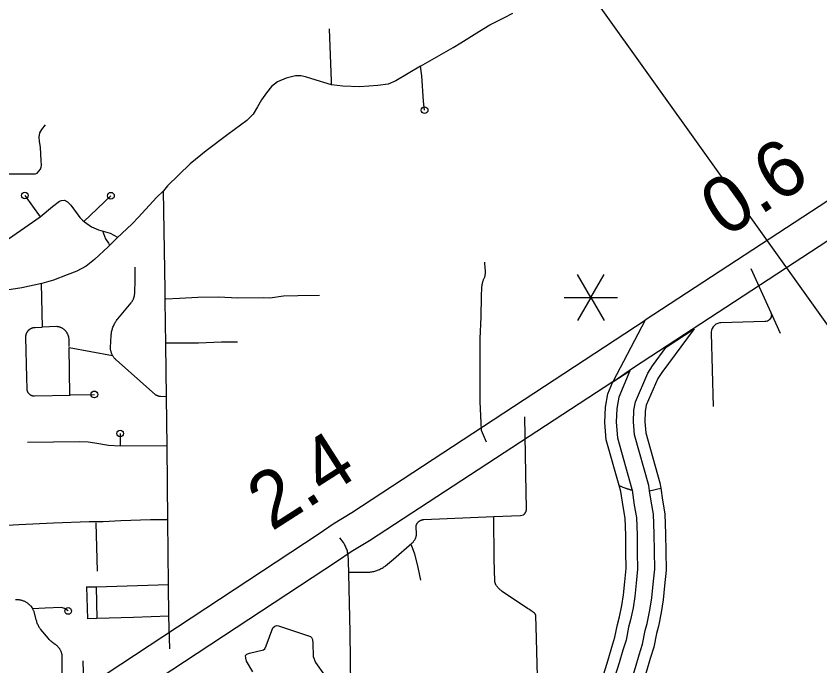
# Model space of a CAD drawing. Extents: x 309348 to 309445, y 336383 to 336484.
# Drawn here: x 309359.624 to 309362.374, y 336391.134 to 336393.355 of the extents above; entities that cross this region are included whole.
import ezdxf

# ---------------------------------------------------------------- set-up
doc = ezdxf.new("R2010")
doc.units = 0
doc.layers.add('R_Annotation', color=7, linetype='Continuous')

msp = doc.modelspace()

# ---------------------------------------------------------------- linework, layer by layer
at = {"layer": 'R_Annotation'}
for p, q in [((309361.5903, 336392.3927), (309361.5448, 336392.4715)), ((309361.5903, 336392.3927), (309361.6357, 336392.4715)), ((309361.4993, 336392.3927), (309361.5903, 336392.3927)), ((309361.5903, 336392.3927), (309361.5448, 336392.314)), ((309361.5903, 336392.3927), (309361.6812, 336392.3927)), ((309361.5903, 336392.3927), (309361.6357, 336392.314)), ((309361.8485, 336392.2227), (309361.9438, 336392.2861)), ((309361.666, 336392.1041), (309361.7243, 336392.1417))]:
    msp.add_line(p, q, dxfattribs=at)
for points in [[(309357.367, 336395.4603), (309360.1377, 336395.4603), (309363.8212, 336390.3132)], [(309367.0035, 336394.3488), (309366.123, 336394.2935), (309364.9553, 336394.2289), (309364.883, 336394.2195), (309364.8281, 336394.2076), (309364.6962, 336394.1686), (309364.597, 336394.1336), (309364.4828, 336394.0765), (309364.3887, 336394.0246), (309364.2, 336393.9054), (309364.1306, 336393.8579), (309362.6846, 336392.9078), (309361.7768, 336392.3157)], [(309361.7768, 336392.3157), (309361.666, 336392.1041), (309361.7366, 336392.1538), (309362.7468, 336392.8127), (309364.194, 336393.7635), (309364.2625, 336393.8105), (309364.4466, 336393.9267), (309364.5357, 336393.9759), (309364.6415, 336394.0288), (309364.7313, 336394.0604), (309364.8563, 336394.0974), (309364.9024, 336394.1074), (309364.9658, 336394.1157), (309366.1297, 336394.18), (309367.0106, 336394.2353)], [(309361.008, 336393.1834), (309361.1195, 336393.2475), (309361.1462, 336393.2636), (309361.2095, 336393.3036), (309361.2455, 336393.3243), (309361.2923, 336393.3491), (309361.324, 336393.3644)], [(309360.703, 336393.1196), (309360.7036, 336393.1323), (309360.6962, 336393.3114)], [(309361.008, 336393.1834), (309360.9229, 336393.133), (309360.8973, 336393.1223), (309360.8617, 336393.1174), (309360.7998, 336393.1131), (309360.7422, 336393.1152), (309360.703, 336393.1196), (309360.6356, 336393.1401), (309360.6142, 336393.1472), (309360.5979, 336393.1508), (309360.5801, 336393.1501), (309360.5481, 336393.143), (309360.5182, 336393.1295), (309360.4976, 336393.1145), (309360.4812, 336393.0925), (309360.4634, 336393.0683), (309360.4499, 336393.0441), (309360.435, 336393.0192), (309360.4137, 336392.9979), (309360.349, 336392.9502), (309360.275, 336392.8947), (309360.2195, 336392.8499), (309360.142, 336392.7745), (309360.1288, 336392.758)], [(309361.0218, 336393.0331), (309361.0181, 336393.0644), (309361.0118, 336393.1508), (309361.008, 336393.1834)], [(309359.5701, 336392.8087), (309359.5751, 336392.8137), (309359.5815, 336392.8153), (309359.6001, 336392.815), (309359.6739, 336392.8153), (309359.6902, 336392.816), (309359.6959, 336392.818), (309359.7019, 336392.8243), (309359.7075, 336392.8316), (309359.7099, 336392.8386), (309359.7109, 336392.8449), (309359.7105, 336392.8609), (309359.7082, 336392.9055), (309359.7042, 336392.9275), (309359.7029, 336392.9414), (309359.7052, 336392.9558), (309359.7122, 336392.9667), (309359.7245, 336392.983)], [(309359.6543, 336392.7415), (309359.7063, 336392.6687)], [(309359.8564, 336392.6528), (309359.9488, 336392.7408)], [(309359.9694, 336392.5958), (309360.0215, 336392.6449), (309360.0434, 336392.6674), (309360.1052, 336392.7341), (309360.1288, 336392.758)], [(309360.1348, 336392.3829), (309360.1344, 336392.4187), (309360.1288, 336392.758)], [(309359.7063, 336392.6687), (309359.7494, 336392.7041), (309359.7733, 336392.7217), (309359.7792, 336392.7246), (309359.7899, 336392.7256), (309359.8002, 336392.7197), (309359.8119, 336392.709), (309359.8427, 336392.666), (309359.851, 336392.6567), (309359.8578, 336392.6518), (309359.8818, 336392.6347), (309359.9062, 336392.6245), (309359.9467, 336392.6122), (309359.9716, 336392.5995)], [(309359.572, 336392.5752), (309359.7063, 336392.6687)], [(309359.9198, 336392.6204), (309359.9301, 336392.5937), (309359.9399, 336392.5781), (309359.9438, 336392.5722)], [(309359.939, 336392.5665), (309359.9694, 336392.5958)], [(309359.939, 336392.5665), (309359.893, 336392.5233), (309359.8637, 336392.5004), (309359.8319, 336392.4833), (309359.7992, 336392.4701), (309359.7523, 336392.452), (309359.7128, 336392.4408), (309359.6439, 336392.4261), (309359.6072, 336392.4203), (309359.5762, 336392.416)], [(309361.2271, 336392.514), (309361.2284, 336392.4911), (309361.2287, 336392.4888), (309361.229, 336392.4866), (309361.2291, 336392.4843), (309361.2292, 336392.4819), (309361.2292, 336392.4796), (309361.2291, 336392.4773), (309361.2289, 336392.475), (309361.2286, 336392.4728), (309361.2283, 336392.4705), (309361.2279, 336392.4682), (309361.2274, 336392.466), (309361.2269, 336392.4637), (309361.2263, 336392.4615), (309361.2256, 336392.4593), (309361.2248, 336392.4571), (309361.2237, 336392.455), (309361.2227, 336392.4528), (309361.2218, 336392.4506), (309361.221, 336392.4483), (309361.2202, 336392.446), (309361.2195, 336392.4437), (309361.2189, 336392.4414), (309361.2184, 336392.4391), (309361.2179, 336392.4367), (309361.2175, 336392.4343), (309361.2172, 336392.4319), (309361.217, 336392.4296), (309361.2168, 336392.4272), (309361.2154, 336392.397), (309361.2137, 336392.3254), (309361.2113, 336392.2526), (309361.2104, 336392.2222), (309361.2105, 336392.1803), (309361.2108, 336392.1076), (309361.2112, 336392.0362), (309361.2138, 336391.9643), (309361.2152, 336391.9392), (309361.2326, 336391.8992)], [(309360.0201, 336392.378), (309360.0211, 336392.3795), (309360.0221, 336392.3811), (309360.023, 336392.3826), (309360.0239, 336392.3842), (309360.0247, 336392.3859), (309360.0255, 336392.3875), (309360.0262, 336392.3892), (309360.0269, 336392.3909), (309360.0275, 336392.3926), (309360.0281, 336392.3944), (309360.0285, 336392.3961), (309360.029, 336392.3979), (309360.0293, 336392.3997), (309360.0296, 336392.4015), (309360.0299, 336392.4033), (309360.0301, 336392.4051), (309360.0302, 336392.407), (309360.0303, 336392.4088), (309360.032, 336392.4523), (309360.0312, 336392.4962)], [(309362.1381, 336392.4923), (309362.2063, 336392.3413), (309362.2067, 336392.3402), (309362.2078, 336392.3366), (309362.2082, 336392.3329), (309362.2079, 336392.3292), (309362.207, 336392.3255), (309362.2055, 336392.3221), (309362.2034, 336392.319), (309362.2008, 336392.3163), (309362.1978, 336392.314), (309362.1944, 336392.3124), (309362.1908, 336392.3113), (309362.1871, 336392.3109), (309362.1859, 336392.311), (309362.0351, 336392.3063), (309362.0306, 336392.3059), (309362.0244, 336392.3042), (309362.0186, 336392.3014), (309362.0134, 336392.2976), (309362.0091, 336392.2928), (309362.0057, 336392.2873), (309362.0034, 336392.2813), (309362.0023, 336392.2749), (309362.0023, 336392.2715), (309362.0089, 336392.0198)], [(309359.7101, 336392.4402), (309359.7133, 336392.2917)], [(309359.9544, 336392.1949), (309359.9535, 336392.1967), (309359.9526, 336392.1986), (309359.9518, 336392.2004), (309359.951, 336392.2024), (309359.9503, 336392.2043), (309359.9497, 336392.2063), (309359.9491, 336392.2082), (309359.9486, 336392.2102), (309359.9482, 336392.2123), (309359.9478, 336392.2143), (309359.9475, 336392.2163), (309359.9473, 336392.2184), (309359.9472, 336392.2204), (309359.9471, 336392.2225), (309359.9495, 336392.2627), (309359.9498, 336392.266), (309359.9502, 336392.2693), (309359.9506, 336392.2725), (309359.9512, 336392.2758), (309359.9519, 336392.279), (309359.9527, 336392.2822), (309359.9536, 336392.2854), (309359.9546, 336392.2885), (309359.9558, 336392.2916), (309359.957, 336392.2947), (309359.9583, 336392.2977), (309359.9597, 336392.3007), (309359.9612, 336392.3036), (309359.9628, 336392.3065), (309359.9646, 336392.3093), (309359.9664, 336392.3121), (309359.9683, 336392.3148), (309359.9702, 336392.3174), (309359.9723, 336392.32), (309360.0178, 336392.3751), (309360.019, 336392.3766), (309360.0201, 336392.378)], [(309360.1366, 336392.2324), (309360.1348, 336392.3829)], [(309360.6627, 336392.3996), (309360.5879, 336392.3991), (309360.5391, 336392.397), (309360.4923, 336392.3902), (309360.4705, 336392.3918), (309360.3832, 336392.3908), (309360.3162, 336392.3944), (309360.2466, 336392.3928), (309360.1832, 336392.3892), (309360.1365, 336392.3877)], [(309362.2063, 336392.3413), (309362.238, 336392.2713)], [(309359.6692, 336392.0633), (309359.6686, 336392.0639), (309359.6681, 336392.0645), (309359.6675, 336392.0651), (309359.667, 336392.0657), (309359.6665, 336392.0664), (309359.6661, 336392.067), (309359.6656, 336392.0677), (309359.6652, 336392.0684), (309359.6648, 336392.0691), (309359.6645, 336392.0698), (309359.6641, 336392.0705), (309359.6638, 336392.0713), (309359.6635, 336392.072), (309359.6633, 336392.0728), (309359.663, 336392.0736), (309359.6628, 336392.0744), (309359.6626, 336392.0751), (309359.6625, 336392.0759), (309359.6624, 336392.0767), (309359.6623, 336392.0775), (309359.6622, 336392.0783), (309359.6621, 336392.0791), (309359.6621, 336392.08), (309359.6621, 336392.0808), (309359.6622, 336392.0816), (309359.6607, 336392.1182), (309359.6578, 336392.2574), (309359.6578, 336392.2586), (309359.6578, 336392.2597), (309359.6579, 336392.2608), (309359.658, 336392.262), (309359.6581, 336392.2631), (309359.6583, 336392.2642), (309359.6586, 336392.2654), (309359.6588, 336392.2665), (309359.6591, 336392.2676), (309359.6595, 336392.2686), (309359.6599, 336392.2697), (309359.6603, 336392.2708), (309359.6608, 336392.2718), (309359.6613, 336392.2729), (309359.6618, 336392.2739), (309359.6624, 336392.2749), (309359.663, 336392.2758), (309359.6636, 336392.2768), (309359.6643, 336392.2777), (309359.665, 336392.2786), (309359.6657, 336392.2795), (309359.6665, 336392.2803), (309359.6672, 336392.2811), (309359.6681, 336392.2819), (309359.6689, 336392.2827), (309359.6698, 336392.2834), (309359.6707, 336392.2841), (309359.6716, 336392.2848), (309359.6725, 336392.2855), (309359.6735, 336392.2861), (309359.6745, 336392.2866), (309359.6755, 336392.2872), (309359.6765, 336392.2877), (309359.6776, 336392.2881), (309359.6786, 336392.2886), (309359.6797, 336392.289), (309359.6808, 336392.2893), (309359.6819, 336392.2896), (309359.683, 336392.2899), (309359.6841, 336392.2901), (309359.6852, 336392.2903), (309359.6863, 336392.2905), (309359.6875, 336392.2906), (309359.6886, 336392.2907), (309359.6897, 336392.2907), (309359.7133, 336392.2917)], [(309359.806, 336392.2252), (309359.8054, 336392.252), (309359.8052, 336392.2536), (309359.805, 336392.2552), (309359.8047, 336392.2568), (309359.8043, 336392.2583), (309359.8039, 336392.2599), (309359.8035, 336392.2614), (309359.8029, 336392.2629), (309359.8024, 336392.2644), (309359.8018, 336392.2659), (309359.8011, 336392.2674), (309359.8004, 336392.2688), (309359.7996, 336392.2702), (309359.7988, 336392.2716), (309359.7979, 336392.273), (309359.797, 336392.2743), (309359.7961, 336392.2756), (309359.7951, 336392.2768), (309359.794, 336392.278), (309359.793, 336392.2792), (309359.7918, 336392.2804), (309359.7907, 336392.2815), (309359.7895, 336392.2825), (309359.7883, 336392.2836), (309359.787, 336392.2845), (309359.7857, 336392.2855), (309359.7844, 336392.2864), (309359.783, 336392.2872), (309359.7816, 336392.288), (309359.7802, 336392.2887), (309359.7788, 336392.2894), (309359.7773, 336392.2901), (309359.7758, 336392.2907), (309359.7743, 336392.2912), (309359.7728, 336392.2917), (309359.7712, 336392.2921), (309359.7697, 336392.2925), (309359.7681, 336392.2929), (309359.7665, 336392.2931), (309359.765, 336392.2934), (309359.7634, 336392.2935), (309359.7133, 336392.2917)], [(309360.6606, 336391.5861), (309360.7087, 336391.6196), (309360.7728, 336391.6579), (309361.7768, 336392.3157), (309361.666, 336392.1041)], [(309361.9438, 336392.2861), (309361.8329, 336392.1371), (309361.8197, 336392.1161), (309361.7803, 336392.0247), (309361.7766, 336392.0031), (309361.7748, 336391.9685), (309361.7782, 336391.9309), (309361.8264, 336391.7593), (309361.8294, 336391.7407)], [(309360.1365, 336392.2385), (309360.2482, 336392.2385), (309360.3271, 336392.2411), (309360.3822, 336392.2411)], [(309359.8087, 336392.0599), (309359.806, 336392.2217)], [(309359.806, 336392.2217), (309359.9544, 336392.1949)], [(309360.1389, 336392.0529), (309360.1366, 336392.2324)], [(309361.7916, 336391.7326), (309361.7886, 336391.7509), (309361.74, 336391.9239), (309361.7361, 336391.9678), (309361.7381, 336392.0074), (309361.743, 336392.0358), (309361.7854, 336392.1342), (309361.801, 336392.159), (309361.8485, 336392.2227)], [(309360.1389, 336392.0529), (309360.1185, 336392.0544), (309360.1173, 336392.0545), (309360.1161, 336392.0547), (309360.1149, 336392.0549), (309360.1137, 336392.0551), (309360.1125, 336392.0554), (309360.1113, 336392.0557), (309360.1101, 336392.056), (309360.109, 336392.0564), (309360.1079, 336392.0569), (309360.1067, 336392.0574), (309360.1056, 336392.0579), (309360.1045, 336392.0584), (309360.1035, 336392.059), (309360.1024, 336392.0596), (309360.1014, 336392.0603), (309360.1004, 336392.061), (309359.9673, 336392.1788), (309359.9658, 336392.1802), (309359.9643, 336392.1816), (309359.9629, 336392.1831), (309359.9615, 336392.1847), (309359.9602, 336392.1863), (309359.9589, 336392.1879), (309359.9577, 336392.1896), (309359.9565, 336392.1913), (309359.9555, 336392.1931), (309359.9544, 336392.1949)], [(309361.7243, 336392.1417), (309361.686, 336392.0528), (309361.6793, 336392.014), (309361.6768, 336391.9667), (309361.6816, 336391.9132), (309361.7308, 336391.7381), (309361.7314, 336391.7342)], [(309361.666, 336392.1041), (309360.8331, 336391.5615), (309360.7704, 336391.524), (309360.7243, 336391.492)], [(309361.6872, 336391.7502), (309361.6435, 336391.9062), (309361.6381, 336391.9659), (309361.6408, 336392.0183), (309361.6487, 336392.0639), (309361.666, 336392.1041)], [(309359.6692, 336392.0633), (309359.6698, 336392.0628), (309359.6704, 336392.0622), (309359.671, 336392.0617), (309359.6716, 336392.0612), (309359.6723, 336392.0608), (309359.673, 336392.0603), (309359.6737, 336392.0599), (309359.6744, 336392.0595), (309359.6751, 336392.0591), (309359.6758, 336392.0588), (309359.6766, 336392.0585), (309359.6773, 336392.0582), (309359.6781, 336392.0579), (309359.6789, 336392.0577), (309359.6796, 336392.0575), (309359.6804, 336392.0573), (309359.6812, 336392.0571), (309359.682, 336392.057), (309359.6828, 336392.0569), (309359.6836, 336392.0568), (309359.6844, 336392.0568), (309359.6852, 336392.0568), (309359.686, 336392.0568), (309359.6868, 336392.0568), (309359.6876, 336392.0569), (309359.8088, 336392.0595)], [(309359.8087, 336392.0599), (309359.892, 336392.0617)], [(309360.1411, 336391.884), (309360.1389, 336392.0529)], [(309361.2588, 336391.6442), (309361.3498, 336391.6474), (309361.3599, 336391.65), (309361.3607, 336391.6506), (309361.3614, 336391.6512), (309361.3621, 336391.6519), (309361.3628, 336391.6526), (309361.3635, 336391.6533), (309361.3642, 336391.6541), (309361.3648, 336391.6548), (309361.3654, 336391.6556), (309361.366, 336391.6564), (309361.3665, 336391.6573), (309361.367, 336391.6581), (309361.3675, 336391.659), (309361.368, 336391.6598), (309361.3684, 336391.6607), (309361.3688, 336391.6616), (309361.3691, 336391.6626), (309361.3694, 336391.6635), (309361.3697, 336391.6644), (309361.37, 336391.6654), (309361.3702, 336391.6664), (309361.3704, 336391.6673), (309361.3706, 336391.6683), (309361.3707, 336391.6693), (309361.3708, 336391.6703), (309361.3708, 336391.6713), (309361.3709, 336391.6722), (309361.3709, 336391.6732), (309361.3692, 336391.7265), (309361.3652, 336391.9855)], [(309359.9804, 336391.9281), (309359.9798, 336391.8849)], [(309360.1411, 336391.8855), (309359.9798, 336391.8849), (309359.9403, 336391.8867), (309359.8935, 336391.8952), (309359.8704, 336391.8983), (309359.8418, 336391.9001), (309359.6637, 336391.8971)], [(309360.1439, 336391.6309), (309360.1411, 336391.884)], [(309361.63, 336391.0922), (309361.6503, 336391.1547), (309361.6622, 336391.1984), (309361.6731, 336391.2318), (309361.6817, 336391.2755), (309361.6885, 336391.301), (309361.6968, 336391.34), (309361.7022, 336391.3769), (309361.7069, 336391.4214), (309361.7112, 336391.467), (309361.7105, 336391.5227), (309361.7098, 336391.5807), (309361.7077, 336391.6389), (309361.7007, 336391.6785), (309361.6928, 336391.7304), (309361.6874, 336391.7501)], [(309361.6874, 336391.7501), (309361.7004, 336391.7449), (309361.7314, 336391.7342)], [(309361.7314, 336391.7342), (309361.7392, 336391.6829), (309361.7466, 336391.6413), (309361.7488, 336391.5803), (309361.7495, 336391.5218), (309361.7502, 336391.4643), (309361.7457, 336391.4168), (309361.7409, 336391.3714), (309361.7352, 336391.3327), (309361.7265, 336391.2918), (309361.7198, 336391.2666), (309361.711, 336391.2219), (309361.6997, 336391.1874), (309361.6879, 336391.1438), (309361.6642, 336391.072)], [(309361.7209, 336391.0552), (309361.7438, 336391.128), (309361.7555, 336391.1713), (309361.7676, 336391.2081), (309361.7767, 336391.2546), (309361.7833, 336391.2793), (309361.7928, 336391.324), (309361.7991, 336391.3662), (309361.804, 336391.4134), (309361.8089, 336391.4649), (309361.8081, 336391.526), (309361.8074, 336391.5853), (309361.805, 336391.6519), (309361.7969, 336391.6973), (309361.7916, 336391.7326)], [(309361.8294, 336391.7407), (309361.8354, 336391.7008), (309361.8439, 336391.6535), (309361.8464, 336391.584), (309361.8471, 336391.5244), (309361.8479, 336391.4614), (309361.8428, 336391.408), (309361.8378, 336391.3599), (309361.8313, 336391.3159), (309361.8214, 336391.2692), (309361.8148, 336391.2448), (309361.8055, 336391.1974), (309361.7931, 336391.1594), (309361.7814, 336391.1163), (309361.7596, 336391.0496)], [(309361.7916, 336391.7326), (309361.8294, 336391.7407)], [(309360.1438, 336391.6332), (309360.084, 336391.6327), (309359.9822, 336391.6301), (309359.9224, 336391.6259), (309359.8741, 336391.6259), (309359.752, 336391.6217), (309359.6336, 336391.616), (309359.5151, 336391.6093), (309359.4372, 336391.6056), (309359.3782, 336391.6019)], [(309360.7635, 336391.4539), (309360.8344, 336391.4547), (309360.8378, 336391.455), (309360.8412, 336391.4555), (309360.8446, 336391.4562), (309360.848, 336391.4569), (309360.8513, 336391.4577), (309360.8546, 336391.4587), (309360.8579, 336391.4597), (309360.8611, 336391.4609), (309360.8643, 336391.4622), (309360.8675, 336391.4636), (309360.8706, 336391.4651), (309360.8736, 336391.4667), (309360.8766, 336391.4684), (309360.8795, 336391.4702), (309360.8824, 336391.4721), (309360.8852, 336391.4741), (309360.8879, 336391.4762), (309360.9156, 336391.4981), (309360.9785, 336391.5531), (309360.9798, 336391.5543), (309360.981, 336391.5555), (309360.9822, 336391.5568), (309360.9833, 336391.5581), (309360.9844, 336391.5594), (309360.9855, 336391.5608), (309360.9865, 336391.5623), (309360.9874, 336391.5637), (309360.9883, 336391.5652), (309360.9892, 336391.5667), (309360.99, 336391.5683), (309360.9907, 336391.5698), (309360.9914, 336391.5715), (309360.992, 336391.5731), (309360.9926, 336391.5747), (309360.9931, 336391.5764), (309360.9935, 336391.5781), (309360.9939, 336391.5798), (309360.9932, 336391.6144), (309360.9936, 336391.6153), (309360.9939, 336391.6163), (309360.9943, 336391.6172), (309360.9948, 336391.6181), (309360.9952, 336391.619), (309360.9957, 336391.6198), (309360.9963, 336391.6207), (309360.9968, 336391.6215), (309360.9974, 336391.6223), (309360.998, 336391.6231), (309360.9986, 336391.6239), (309360.9993, 336391.6247), (309361, 336391.6254), (309361.0007, 336391.6261), (309361.0015, 336391.6268), (309361.0022, 336391.6274), (309361.003, 336391.6281), (309361.0038, 336391.6287), (309361.0046, 336391.6292), (309361.0055, 336391.6298), (309361.0063, 336391.6303), (309361.0072, 336391.6308), (309361.0081, 336391.6312), (309361.009, 336391.6317), (309361.0099, 336391.6321), (309361.0109, 336391.6324), (309361.0118, 336391.6327), (309361.0128, 336391.633), (309361.0137, 336391.6333), (309361.0147, 336391.6335), (309361.0157, 336391.6337), (309361.0167, 336391.6339), (309361.0177, 336391.634), (309361.0187, 336391.6341), (309361.0197, 336391.6342), (309361.2588, 336391.6442)], [(309361.4079, 336391.0986), (309361.4035, 336391.2684), (309361.4024, 336391.3037), (309361.4024, 336391.3042), (309361.4024, 336391.3047), (309361.4023, 336391.3052), (309361.4022, 336391.3057), (309361.4022, 336391.3062), (309361.402, 336391.3066), (309361.4019, 336391.3071), (309361.4018, 336391.3076), (309361.4016, 336391.3081), (309361.4015, 336391.3085), (309361.4013, 336391.309), (309361.4011, 336391.3095), (309361.4008, 336391.3099), (309361.4006, 336391.3104), (309361.4004, 336391.3108), (309361.4001, 336391.3112), (309361.3998, 336391.3116), (309361.3995, 336391.312), (309361.3992, 336391.3124), (309361.3989, 336391.3128), (309361.3986, 336391.3132), (309361.3982, 336391.3135), (309361.3944, 336391.3166), (309361.3905, 336391.3196), (309361.3865, 336391.3224), (309361.3823, 336391.3251), (309361.3782, 336391.3277), (309361.3739, 336391.3301), (309361.2872, 336391.3886), (309361.2852, 336391.39), (309361.2832, 336391.3915), (309361.2813, 336391.393), (309361.2795, 336391.3946), (309361.2777, 336391.3963), (309361.276, 336391.398), (309361.2743, 336391.3998), (309361.2727, 336391.4017), (309361.2712, 336391.4035), (309361.2697, 336391.4055), (309361.2683, 336391.4075), (309361.2669, 336391.4095), (309361.2664, 336391.4104), (309361.2659, 336391.4114), (309361.2654, 336391.4123), (309361.2649, 336391.4133), (309361.2645, 336391.4143), (309361.2641, 336391.4153), (309361.2637, 336391.4163), (309361.2634, 336391.4174), (309361.2631, 336391.4184), (309361.2628, 336391.4194), (309361.2626, 336391.4205), (309361.2624, 336391.4216), (309361.2623, 336391.4226), (309361.2622, 336391.4237), (309361.2603, 336391.4991), (309361.2588, 336391.6442)], [(309359.9028, 336391.4581), (309359.8979, 336391.6223)], [(309360.1462, 336391.4118), (309360.1439, 336391.6309)], [(309358.6196, 336390.7983), (309359.2416, 336390.823), (309359.2969, 336390.828), (309359.3664, 336390.8376), (309359.4438, 336390.8539), (309359.5784, 336390.8962), (309359.623, 336390.9154), (309359.71, 336390.9623), (309359.8353, 336391.0432), (309360.6606, 336391.5861)], [(309360.7626, 336391.4501), (309360.7617, 336391.4916), (309360.76, 336391.5153), (309360.7592, 336391.5188), (309360.7584, 336391.5224), (309360.7575, 336391.5259), (309360.7564, 336391.5294), (309360.7552, 336391.5328), (309360.7539, 336391.5362), (309360.7525, 336391.5396), (309360.751, 336391.5429), (309360.7494, 336391.5462), (309360.7477, 336391.5494), (309360.7459, 336391.5525), (309360.7439, 336391.5556), (309360.7319, 336391.571)], [(309360.9762, 336391.5481), (309360.9868, 336391.5165), (309360.9981, 336391.4705), (309361.0074, 336391.4274)], [(309360.7243, 336391.492), (309359.8974, 336390.9479), (309359.7678, 336390.8643), (309359.6725, 336390.8129), (309359.618, 336390.7895), (309359.4726, 336390.7438), (309359.3859, 336390.7255), (309359.3098, 336390.7151), (309359.249, 336390.7095), (309358.5295, 336390.6809), (309358.5127, 336390.6803)], [(309360.77, 336391.065), (309360.7671, 336391.2481), (309360.7626, 336391.4501)], [(309359.8657, 336391.4035), (309359.8977, 336391.4044), (309360.1462, 336391.4118)], [(309360.1469, 336391.304), (309360.1462, 336391.4118)], [(309359.8657, 336391.4035), (309359.8683, 336391.2951)], [(309359.8977, 336391.4044), (309359.9003, 336391.2959)], [(309359.6224, 336391.3608), (309359.6246, 336391.3609), (309359.6269, 336391.3609), (309359.6291, 336391.3608), (309359.6313, 336391.3606), (309359.6336, 336391.3604), (309359.6358, 336391.36), (309359.638, 336391.3596), (309359.6402, 336391.3592), (309359.6424, 336391.3586), (309359.6445, 336391.358), (309359.6466, 336391.3573), (309359.6487, 336391.3565), (309359.6508, 336391.3557), (309359.6529, 336391.3547), (309359.6549, 336391.3537), (309359.6568, 336391.3527), (309359.6588, 336391.3516), (309359.6607, 336391.3504), (309359.6625, 336391.3491), (309359.6643, 336391.3478), (309359.6661, 336391.3464), (309359.6678, 336391.345), (309359.6695, 336391.3435), (309359.6711, 336391.3419), (309359.6727, 336391.3403), (309359.6742, 336391.3386), (309359.6756, 336391.3369), (309359.6819, 336391.3277)], [(309359.8023, 336391.3215), (309359.7904, 336391.3302), (309359.7798, 336391.3333), (309359.7236, 336391.3308), (309359.6808, 336391.3293)], [(309359.782, 336391.1103), (309359.7818, 336391.1724), (309359.7813, 336391.1743), (309359.7808, 336391.1762), (309359.7802, 336391.1781), (309359.7796, 336391.1799), (309359.7789, 336391.1818), (309359.7781, 336391.1836), (309359.7773, 336391.1854), (309359.7764, 336391.1871), (309359.7755, 336391.1888), (309359.7745, 336391.1905), (309359.7734, 336391.1922), (309359.7723, 336391.1938), (309359.7711, 336391.1954), (309359.7699, 336391.1969), (309359.7686, 336391.1984), (309359.7673, 336391.1999), (309359.7659, 336391.2013), (309359.7645, 336391.2026), (309359.763, 336391.2039), (309359.7615, 336391.2052), (309359.7599, 336391.2064), (309359.7583, 336391.2075), (309359.7567, 336391.2086), (309359.755, 336391.2097), (309359.7533, 336391.2106), (309359.75, 336391.2131), (309359.7467, 336391.2157), (309359.7436, 336391.2184), (309359.7405, 336391.2212), (309359.7376, 336391.2241), (309359.7347, 336391.2271), (309359.709, 336391.2578), (309359.7072, 336391.2603), (309359.7055, 336391.2629), (309359.7038, 336391.2656), (309359.7022, 336391.2684), (309359.7007, 336391.2711), (309359.6993, 336391.274), (309359.6981, 336391.2769), (309359.6969, 336391.2798), (309359.6958, 336391.2827), (309359.6948, 336391.2857), (309359.6939, 336391.2887), (309359.6931, 336391.2918), (309359.6884, 336391.3112), (309359.6878, 336391.3134), (309359.6872, 336391.3155), (309359.6865, 336391.3176), (309359.6857, 336391.3197), (309359.6849, 336391.3217), (309359.6839, 336391.3237), (309359.683, 336391.3257), (309359.6819, 336391.3277)], [(309360.1469, 336391.304), (309360.026, 336391.2989), (309359.9003, 336391.2959), (309359.8683, 336391.2951)], [(309360.1498, 336391.1926), (309360.1469, 336391.304)], [(309360.4343, 336391.1141), (309360.413, 336391.1505), (309360.4101, 336391.1597), (309360.4096, 336391.1694), (309360.414, 336391.1742), (309360.4232, 336391.1771), (309360.4702, 336391.1883), (309360.475, 336391.1926), (309360.4794, 336391.2023), (309360.5021, 336391.2634), (309360.5089, 336391.2692), (309360.5157, 336391.2716), (309360.5225, 336391.2711), (309360.631, 336391.2343), (309360.6349, 336391.2309), (309360.6378, 336391.2246), (309360.6397, 336391.2115), (309360.6402, 336391.1665), (309360.6489, 336391.1452), (309360.6789, 336391.102)], [(309359.8526, 336391.1512), (309359.8555, 336391.0328), (309359.8603, 336391.0002)]]:
    msp.add_lwpolyline(points, dxfattribs=at)
for centre in [(309361.0218, 336393.0331), (309359.6543, 336392.7415), (309359.9488, 336392.7408), (309359.892, 336392.0617), (309359.9804, 336391.9281), (309359.8023, 336391.3215)]:
    msp.add_circle(centre, 0.0114, dxfattribs=at)
for centre, radius, start, end in [((309361.8116, 336392.0241), 0.3008, 245.578, 254.5407), ((309361.8116, 336392.0241), 0.3008, 245.578, 254.5407), ((309361.7176, 336392.1718), 0.4453, 279.5618, 284.542), ((309361.7176, 336392.1718), 0.4453, 279.5618, 284.542)]:
    msp.add_arc(centre, radius, start, end, dxfattribs=at)

# ---------------------------------------------------------------- texts
for s, rotation, p in [('0.6', 33.1144, (309362.0495, 336392.5941)), ('2.4', 32.5935, (309360.4983, 336391.5921))]:
    msp.add_text(s, height=0.19206, rotation=rotation, dxfattribs=at).set_placement(p)

doc.saveas('drawing.dxf')
